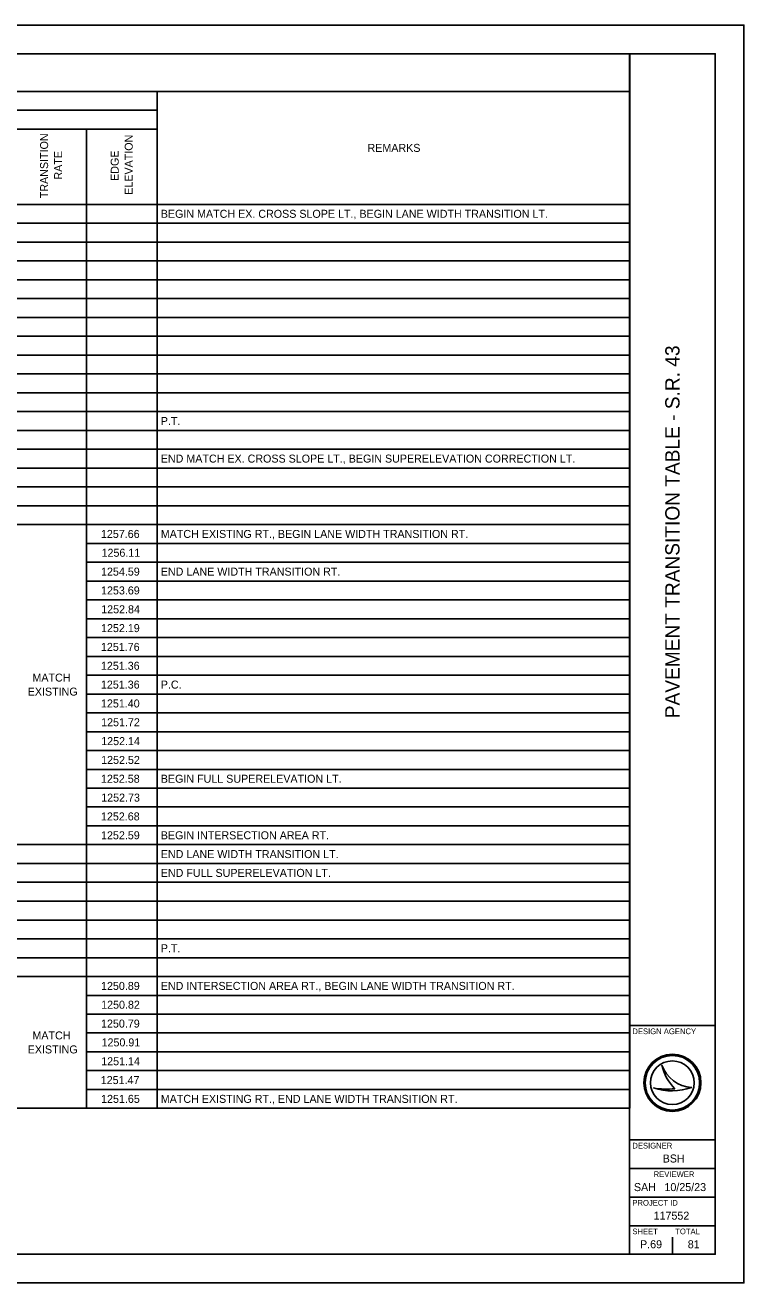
# Model space of a CAD drawing. Extents: x 0 to 34, y 0 to 22.
# Drawn here: x 21.43 to 34, y 0 to 22 of the extents above; entities that cross this region are included whole.
import ezdxf

# ---------------------------------------------------------------- set-up
doc = ezdxf.new("R2010")
doc.units = 0
for name, color, linetype in [('SH_Border', 7, 'Continuous'), ('SH_Cut_Line', 7, 'Continuous'), ('SH_Data', 7, 'Continuous'), ('SH_Text', 7, 'Continuous')]:
    doc.layers.add(name, color=color, linetype=linetype)

msp = doc.modelspace()

# ---------------------------------------------------------------- linework, layer by layer
at = {"layer": 'SH_Border'}
for p, q in [((32, 0.5), (32, 21.5)), ((32, 4.5), (33.5, 4.5)), ((32, 2.5), (33.5, 2.5)), ((32, 2), (33.5, 2)), ((32, 1.5), (33.5, 1.5)), ((32, 1), (33.5, 1))]:
    msp.add_line(p, q, dxfattribs=at)
msp.add_lwpolyline([(1.5, 21.5), (33.5, 21.5), (33.5, 0.5), (1.5, 0.5)], close=True, dxfattribs=at)
at = {"layer": 'SH_Cut_Line'}
msp.add_lwpolyline([(0, 0), (34, 0), (34, 22), (0, 22)], close=True, dxfattribs=at)
at = {"layer": 'SH_Data'}
for p, q in [((32.567, 3.81), (32.567, 3.81)), ((32.417, 3.41), (32.417, 3.41)), ((32.75, 3.5), (32.75, 3.5)), ((33.087, 3.419), (33.087, 3.419)), ((32.375, 0.675), (32.375, 0.675)), ((32.75, 0.5), (32.75, 0.8))]:
    msp.add_line(p, q, dxfattribs=at)
for radius in [0.5, 0.477, 0.477, 0.382]:
    msp.add_circle((32.75, 3.5), radius, dxfattribs=at)
for centre, radius, start, end in [((33.116, 3.998), 0.58, 198.9257, 198.9319), ((33.347, 3.97), 0.796, 191.6379, 191.6421), ((33.116, 3.998), 0.58, 198.9319, 267.1657), ((33.347, 3.97), 0.796, 191.6421, 226.0947), ((32.739, 4.37), 1.013, 251.4576, 290.0832), ((32.648, 4.654), 1.266, 259.4964, 259.4995), ((32.739, 4.37), 1.013, 251.4527, 251.4576), ((32.648, 4.654), 1.266, 259.4995, 276.6672)]:
    msp.add_arc(centre, radius, start, end, dxfattribs=at)
at = {"layer": 'SH_Text'}
for p, q in [((1.5, 21.5), (32.004, 21.5)), ((32.004, 21.5), (32.004, 3.053)), ((1.5, 20.841), (32.004, 20.841)), ((23.735, 20.841), (23.735, 3.053)), ((13.853, 20.512), (23.735, 20.512)), ((1.5, 20.182), (23.735, 20.182)), ((22.5, 20.182), (22.5, 3.053)), ((1.5, 18.865), (32.004, 18.865)), ((3.971, 18.535), (32.004, 18.535)), ((3.971, 18.206), (32.004, 18.206)), ((3.971, 17.876), (32.004, 17.876)), ((3.971, 17.547), (32.004, 17.547)), ((3.971, 17.218), (32.004, 17.218)), ((3.971, 16.888), (32.004, 16.888)), ((3.971, 16.559), (32.004, 16.559)), ((3.971, 16.229), (32.004, 16.229)), ((3.971, 15.9), (32.004, 15.9)), ((3.971, 15.571), (32.004, 15.571)), ((3.971, 15.241), (32.004, 15.241)), ((3.971, 14.912), (32.004, 14.912)), ((1.5, 14.582), (32.004, 14.582)), ((3.971, 14.253), (32.004, 14.253)), ((3.971, 13.924), (32.004, 13.924)), ((3.971, 13.594), (32.004, 13.594)), ((3.971, 13.265), (32.004, 13.265)), ((22.5, 12.935), (32.004, 12.935)), ((22.5, 12.606), (32.004, 12.606)), ((22.5, 12.276), (32.004, 12.276)), ((22.5, 11.947), (32.004, 11.947)), ((22.5, 11.618), (32.004, 11.618)), ((22.5, 11.288), (32.004, 11.288)), ((22.5, 10.959), (32.004, 10.959)), ((22.5, 10.629), (32.004, 10.629)), ((22.5, 10.3), (32.004, 10.3)), ((22.5, 9.971), (32.004, 9.971)), ((22.5, 9.641), (32.004, 9.641)), ((22.5, 9.312), (32.004, 9.312)), ((22.5, 8.982), (32.004, 8.982)), ((22.5, 8.653), (32.004, 8.653)), ((22.5, 8.324), (32.004, 8.324)), ((22.5, 7.994), (32.004, 7.994)), ((3.971, 7.665), (32.004, 7.665)), ((1.5, 7.335), (32.004, 7.335)), ((3.971, 7.006), (32.004, 7.006)), ((3.971, 6.676), (32.004, 6.676)), ((3.971, 6.347), (32.004, 6.347)), ((3.971, 6.018), (32.004, 6.018)), ((3.971, 5.688), (32.004, 5.688)), ((3.971, 5.359), (32.004, 5.359)), ((22.5, 5.029), (32.004, 5.029)), ((22.5, 4.7), (32.004, 4.7)), ((22.5, 4.371), (32.004, 4.371)), ((22.5, 4.041), (32.004, 4.041)), ((22.5, 3.712), (32.004, 3.712)), ((22.5, 3.382), (32.004, 3.382)), ((1.5, 3.053), (32.004, 3.053))]:
    msp.add_line(p, q, dxfattribs=at)

# ---------------------------------------------------------------- texts
at = {"layer": 'SH_Data'}
msp.add_text('PAVEMENT TRANSITION TABLE - S.R. 43', height=0.25, rotation=90, dxfattribs=at).set_placement((32.875, 9.877))
for s, height, p in [('DESIGN AGENCY', 0.1, (32.05, 4.35)), ('DESIGNER', 0.1, (32.05, 2.35)), ('BSH', 0.14, (32.58, 2.105)), ('REVIEWER', 0.1, (32.422, 1.85)), ('SAH', 0.14, (32.077, 1.605)), ('10/25/23', 0.14, (32.611, 1.605)), ('PROJECT ID', 0.1, (32.05, 1.35)), ('117552', 0.14, (32.421, 1.105)), ('SHEET', 0.1, (32.05, 0.85)), ('TOTAL', 0.1, (32.8, 0.85)), ('P.69', 0.14, (32.184, 0.605)), ('81', 0.14, (33.019, 0.605))]:
    msp.add_text(s, height=height, dxfattribs=at).set_placement(p)
at = {"layer": 'SH_Text'}
for s, p in [('TRANSITION', (21.83, 18.973)), ('ELEVATION', (23.31, 19.033)), ('RATE', (22.075, 19.299)), ('EDGE', (23.065, 19.276))]:
    msp.add_text(s, height=0.14, rotation=90, dxfattribs=at).set_placement(p)
for s, p in [('REMARKS', (27.417, 19.783)), ('BEGIN MATCH EX. CROSS SLOPE LT., BEGIN LANE WIDTH TRANSITION LT.', (23.801, 18.63)), ('P.T.', (23.801, 15.006)), ('END MATCH EX. CROSS SLOPE LT., BEGIN SUPERELEVATION CORRECTION LT.', (23.801, 14.348)), ('1257.66', (22.754, 13.03)), ('MATCH EXISTING RT., BEGIN LANE WIDTH TRANSITION RT.', (23.801, 13.03)), ('1256.11', (22.765, 12.701)), ('1254.59', (22.756, 12.371)), ('END LANE WIDTH TRANSITION RT.', (23.801, 12.371)), ('1253.69', (22.756, 12.042)), ('1252.84', (22.759, 11.712)), ('1252.19', (22.756, 11.383)), ('1251.76', (22.754, 11.054)), ('1251.36', (22.754, 10.724)), ('MATCH ', (21.556, 10.517)), ('EXISTING', (21.473, 10.272)), ('1251.36', (22.754, 10.395)), ('P.C.', (23.801, 10.395)), ('1251.40', (22.755, 10.065)), ('1251.72', (22.758, 9.736)), ('1252.14', (22.759, 9.406)), ('1252.52', (22.758, 9.077)), ('1252.58', (22.755, 8.748)), ('BEGIN FULL SUPERELEVATION LT.', (23.801, 8.748)), ('1252.73', (22.759, 8.418)), ('1252.68', (22.755, 8.089)), ('1252.59', (22.756, 7.759)), ('BEGIN INTERSECTION AREA RT.', (23.801, 7.759)), ('END LANE WIDTH TRANSITION LT.', (23.801, 7.43)), ('END FULL SUPERELEVATION LT.', (23.801, 7.101)), ('P.T.', (23.801, 5.783)), ('1250.89', (22.756, 5.124)), ('END INTERSECTION AREA RT., BEGIN LANE WIDTH TRANSITION RT.', (23.801, 5.124)), ('1250.82', (22.758, 4.795)), ('MATCH ', (21.556, 4.258)), ('1250.79', (22.756, 4.465)), ('1250.91', (22.765, 4.136)), ('EXISTING', (21.473, 4.013)), ('1251.14', (22.759, 3.806)), ('1251.47', (22.751, 3.477)), ('1251.65', (22.757, 3.148)), ('MATCH EXISTING RT., END LANE WIDTH TRANSITION RT.', (23.801, 3.148))]:
    msp.add_text(s, height=0.14, dxfattribs=at).set_placement(p)

doc.saveas('drawing.dxf')
